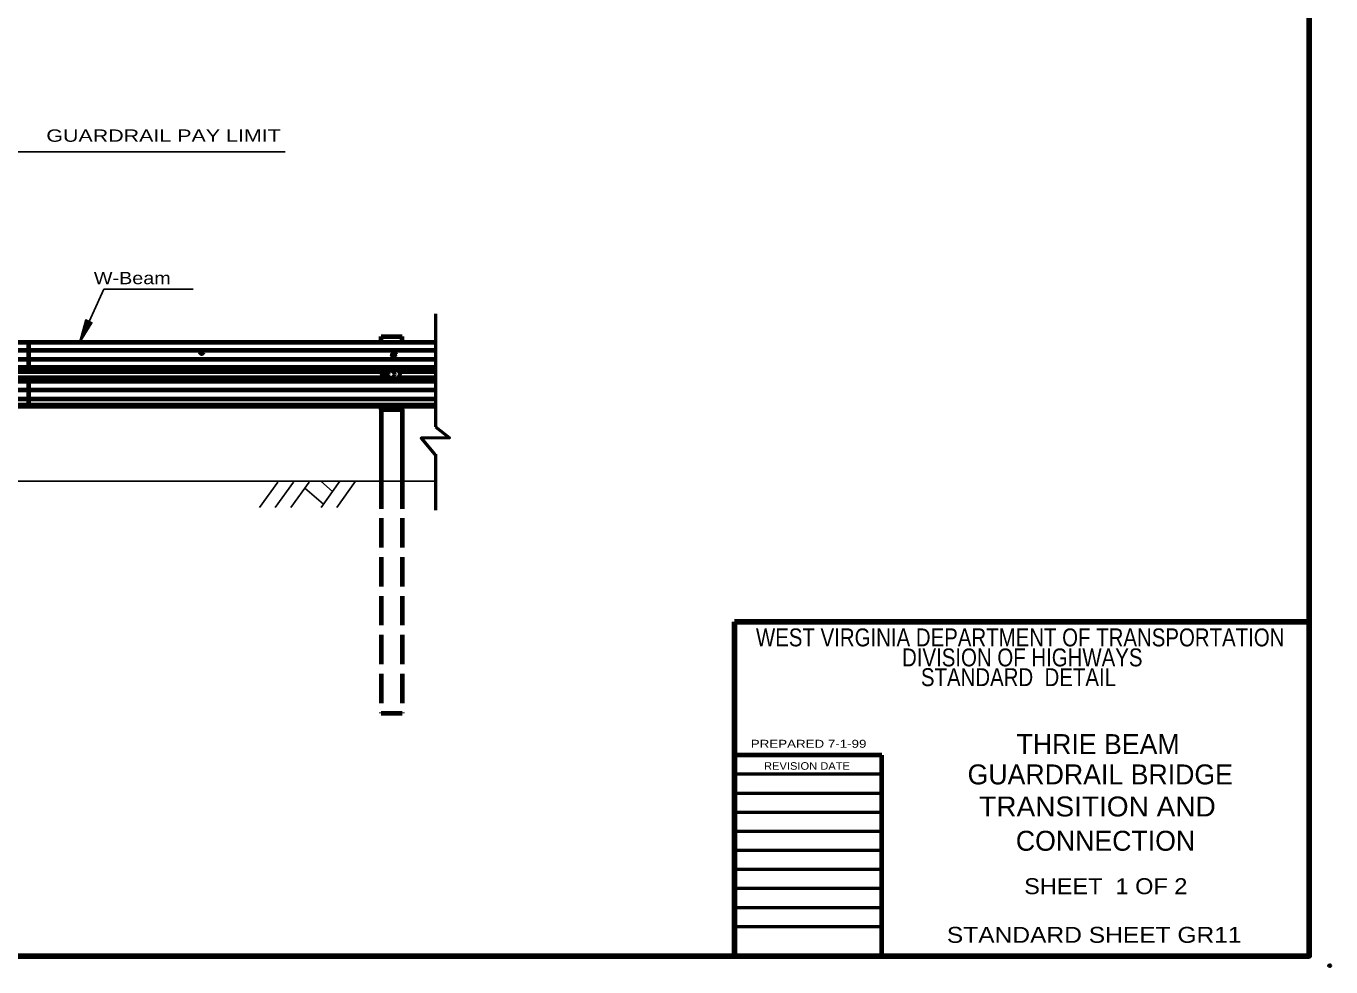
# Model space of a CAD drawing. Extents: x 856.9 to 891.7, y -2278.5 to -2254.7.
# Drawn here: x 877.8 to 891.43, y -2277.28 to -2267.45 of the extents above; entities that cross this region are included whole.
import ezdxf
from ezdxf.enums import TextEntityAlignment as Align

# ---------------------------------------------------------------- set-up
doc = ezdxf.new("R2010")
doc.units = 0
doc.header["$LTSCALE"] = 0.051
doc.header["$PDMODE"] = 32
doc.header["$PDSIZE"] = 0.0255
doc.linetypes.add('LONG_DASHED', pattern=[7.5, 6, -1.5])
for name, color, linetype, lineweight in [('1', 7, 'Continuous', 70), ('3', 7, 'Continuous', 40), ('35', 7, 'Continuous', 70)]:
    doc.layers.add(name, color=color, linetype=linetype, lineweight=lineweight)
doc.layers.add('5', color=7, linetype='Continuous')

msp = doc.modelspace()

# ---------------------------------------------------------------- linework, layer by layer
at = {"layer": '1', "lineweight": 25}
for p, q in [((877.53042, -2268.76158), (880.50733, -2268.76158)), ((878.614, -2270.19842), (879.54567, -2270.19842)), ((862.12625, -2272.20317), (882.07667, -2272.20317)), ((880.23892, -2272.4775), (880.43008, -2272.21158)), ((880.40275, -2272.4775), (880.59392, -2272.21158)), ((880.56633, -2272.4775), (880.75767, -2272.21158)), ((881.00325, -2272.30925), (880.87942, -2272.20242)), ((880.88217, -2272.4775), (881.07992, -2272.20242)), ((881.04583, -2272.4775), (881.2435, -2272.20242)), ((880.90758, -2272.44283), (880.71233, -2272.27458))]:
    msp.add_line(p, q, dxfattribs=at)
at = {"layer": '1', "lineweight": 53}
for p, q in [((882.07667, -2270.45367), (882.07667, -2271.63408)), ((882.07667, -2271.92217), (882.07667, -2272.50433))]:
    msp.add_line(p, q, dxfattribs=at)
at = {"layer": '1'}
for p, q in [((877.175, -2270.75233), (882.07667, -2270.75233)), ((877.175, -2270.833), (882.07667, -2270.833)), ((877.175, -2270.92717), (882.07667, -2270.92717)), ((877.175, -2271.01367), (882.07667, -2271.01367)), ((877.6105, -2271.05683), (879.466, -2271.05683)), ((879.466, -2271.05683), (881.52725, -2271.05683)), ((881.69083, -2271.05683), (882.07667, -2271.05683)), ((881.69083, -2271.1185), (882.07667, -2271.1185)), ((877.175, -2271.2475), (882.07667, -2271.2475)), ((877.17242, -2271.42042), (882.07667, -2271.42042)), ((882.07667, -2271.41067), (877.17383, -2271.41067)), ((877.175, -2271.34183), (882.07667, -2271.34183)), ((881.51017, -2271.45458), (881.51017, -2272.18417)), ((881.72833, -2271.45458), (881.72833, -2272.18417))]:
    msp.add_line(p, q, dxfattribs=at)
at = {"layer": '1', "linetype": 'LONG_DASHED'}
for p, q in [((877.83058, -2271.42308), (877.83058, -2270.75233)), ((881.51017, -2272.18417), (881.51017, -2274.62525)), ((881.72833, -2272.18417), (881.72833, -2274.62525)), ((881.51017, -2274.62525), (881.72833, -2274.62525))]:
    msp.add_line(p, q, dxfattribs=at)
at = {"layer": '1', "lineweight": 25}
for points in [[(878.614, -2270.19842), (878.361, -2270.75758), (878.49075, -2270.548), (878.4265, -2270.51925), (878.361, -2270.75758)], [(878.4745, -2270.54075), (878.38608, -2270.702), (878.44308, -2270.5265)], [(878.46658, -2270.53692), (878.42408, -2270.61358), (878.45083, -2270.52958)]]:
    msp.add_lwpolyline(points, dxfattribs=at)
at = {"layer": '1'}
for points in [[(877.175, -2271.15917), (877.38067, -2271.15917), (882.07667, -2271.15917)], [(877.61192, -2271.1185), (879.466, -2271.1185), (881.52725, -2271.1185)]]:
    msp.add_lwpolyline(points, dxfattribs=at)
at = {"layer": '1', "lineweight": 53}
msp.add_lwpolyline([(882.07667, -2271.63408), (882.22525, -2271.74858), (881.92875, -2271.75383), (882.07217, -2271.92275)], dxfattribs=at)
at = {"layer": '1', "lineweight": 60}
msp.add_circle((881.60937, -2271.08712), 0.03923, dxfattribs=at)
for major_axis, ratio in [((-0.09753, 0), 0.442883), ((0.09753, 0), 0.696674)]:
    msp.add_ellipse((881.61049, -2271.0778), major_axis=major_axis, ratio=ratio, start_param=3.14159265, end_param=6.28318531, dxfattribs=at)
at = {"layer": '1'}
for p in [(879.63508, -2270.86042), (881.6385, -2270.88408), (881.64775, -2270.87883), (881.57033, -2271.08508)]:
    msp.add_point(p, dxfattribs=at)
at = {"layer": '3', "lineweight": 106}
for p in [(891.2, -2273.6735), (885.2, -2277.16333)]:
    msp.add_line(p, (885.2, -2273.6735), dxfattribs=at)
at = {"layer": '3', "lineweight": 53}
for p, q in [((891.2, -2277.16333), (891.2, -2274.66433)), ((886.73792, -2275.26433), (885.2, -2275.26433)), ((886.73792, -2275.46333), (885.2, -2275.46333)), ((886.73792, -2275.66233), (885.2, -2275.66233)), ((885.2, -2275.75333), (885.2, -2277.16333)), ((886.73792, -2275.86133), (885.2, -2275.86133)), ((886.73792, -2276.06033), (885.2, -2276.06033)), ((886.73792, -2276.25933), (885.2, -2276.25933)), ((886.73792, -2276.45833), (885.2, -2276.45833)), ((886.73792, -2276.65733), (885.2, -2276.65733)), ((886.73792, -2276.85633), (885.2, -2276.85633)), ((891.2, -2277.16333), (885.2, -2277.16333))]:
    msp.add_line(p, q, dxfattribs=at)
at = {"layer": '3', "lineweight": 70}
for p, q in [((886.73792, -2275.06433), (885.2, -2275.06433)), ((886.73792, -2277.16333), (886.73792, -2275.06433))]:
    msp.add_line(p, q, dxfattribs=at)
at = {"layer": '3', "lineweight": 158}
msp.add_lwpolyline([(891.2, -2256.16333), (891.2, -2277.16333), (858.7, -2277.16333)], dxfattribs=at)
at = {"layer": '3'}
for p in [(891.2, -2277.16333), (891.413, -2277.26333)]:
    msp.add_point(p, dxfattribs=at)
at = {"layer": '35'}
for p, q in [((881.51017, -2270.69083), (881.72833, -2270.69083)), ((881.51017, -2270.73867), (881.51017, -2270.69083)), ((881.72833, -2270.73867), (881.72833, -2270.69083)), ((881.51017, -2271.45458), (881.51017, -2271.40675)), ((881.72833, -2271.45458), (881.72833, -2271.40675)), ((881.51017, -2271.45458), (881.72833, -2271.45458))]:
    msp.add_line(p, q, dxfattribs=at)

# ---------------------------------------------------------------- texts
at = {"layer": '1'}
for s, width, p in [('GUARDRAIL PAY LIMIT', 1.3, (878.01458, -2268.658)), (' W-Beam', 1.2, (878.45317, -2270.14575))]:
    msp.add_text(s, height=0.1286, dxfattribs=dict(at, width=width)).set_placement(p)
at = {"layer": '3'}
for s, height, width, p in [('WEST VIRGINIA DEPARTMENT OF TRANSPORTATION', 0.1875, 0.85, (888.18175, -2273.92842)), ('DIVISION OF HIGHWAYS', 0.1875, 0.85, (888.20362, -2274.13733)), ('STANDARD  DETAIL', 0.1875, 0.85, (888.16371, -2274.34383)), ('PREPARED 7-1-99', 0.08333, 1.25, (885.97271, -2274.98733)), (' SHEET  1 OF 2      ', 0.1667, 1.1, (889.24579, -2276.51642)), ('STANDARD SHEET GR11', 0.1667, 1.15, (888.95454, -2277.02458))]:
    msp.add_text(s, height=height, dxfattribs=dict(at, width=width)).set_placement(p, align=Align.CENTER)
at = {"layer": '3', "width": 1.1}
msp.add_text('REVISION DATE', height=0.079, dxfattribs=at).set_placement((885.50708, -2275.217))
at = {"layer": '5'}
for s, p in [('THRIE BEAM', (888.99512, -2275.05333)), ('GUARDRAIL BRIDGE', (889.01779, -2275.36975)), ('CONNECTION', (889.07275, -2276.06292))]:
    msp.add_text(s, height=0.2083, dxfattribs=at).set_placement(p, align=Align.CENTER)
at = {"layer": '5', "width": 1.05}
msp.add_text('TRANSITION AND', height=0.2083, dxfattribs=at).set_placement((888.98871, -2275.70467), align=Align.CENTER)

doc.saveas('drawing.dxf')
